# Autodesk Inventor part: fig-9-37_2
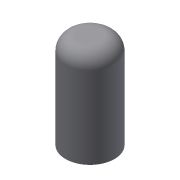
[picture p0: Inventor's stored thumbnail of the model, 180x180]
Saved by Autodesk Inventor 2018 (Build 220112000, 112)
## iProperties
Created: 2013-03
Part Number: fig-9-37_2
Material: Generic
Document SubType Name: Modeling
Designer: CADCIM
Density: 1 g/cm^3
Appearance: Default
Author: CADCIM
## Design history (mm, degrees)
sketch "Sketch1"
  geometry: C1 r 9 at (0, 0); 1 further point
  constraints: 1 centre point, 1 coincident
  dimensions: "d0" = 18 diameter of C1
extrude "Extrusion1" new body sketch "Sketch1" distance "d2" = 35; taper "d3" = 0 deg
fillet "Fillet1" dims "d4" = 5
body "Solid1"
